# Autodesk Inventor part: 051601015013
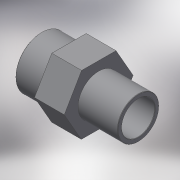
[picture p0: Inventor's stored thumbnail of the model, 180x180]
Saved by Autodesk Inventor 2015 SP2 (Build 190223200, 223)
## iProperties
Created: 2017-10
Part Number: 051601015013
Material: Generic
Description: PLASSON THR. REDUCING NIPPLE 1.1/2"-1.1/4" PVC
Document SubType Name: Modeling
Designer: KIM
Density: 1 g/cm^3
Appearance: Default
Author: KIM
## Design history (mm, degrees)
derived "051601.ipt"
feature "Solid1::051601.ipt"
tag "TaggingFeature1"
body "Solid1"
other parameters: "d13" = 0, "d14" = 0.4191, "d17" = 22, "d18" = 26.4, "d19" = 47.803, "d21" = 41.91, "d23" = 38.2424, "d24" = 33.528, "d25" = 22, "d26" = -22, "R_1" = 41.91, "lt_1" = 22, "lt_" = 22, "R_" = 47.803
